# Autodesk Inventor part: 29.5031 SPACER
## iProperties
Created: 2006-12
Part Number: 29.5031 SPACER
Material: Steel
Document SubType Name: Modeling
Designer: Andy Moles
Density: 7.85 g/cm^3
Author: Andy Moles
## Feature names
1. Extrusion1
2. Extrusion2
3. Hole1
